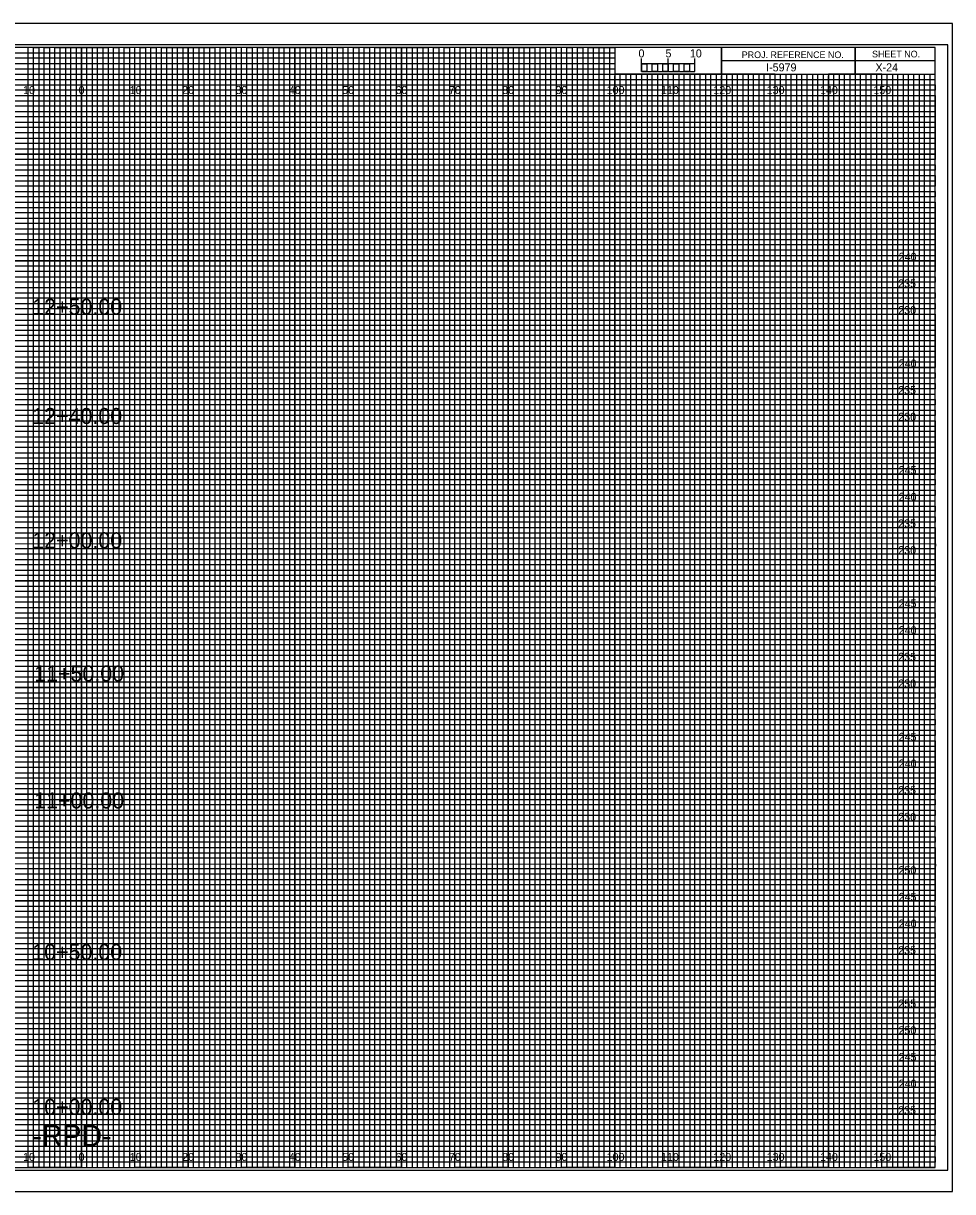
# Model space of a CAD drawing. Extents: x -13 to 323, y -5 to 215.
# Drawn here: x 149.1 to 323.3, y -4.5 to 214.5 of the extents above; entities that cross this region are included whole.
import ezdxf

# ---------------------------------------------------------------- set-up
doc = ezdxf.new("R2010")
doc.units = 0
for name, color, linetype in [('Exist CMT Pavement', 7, 'Continuous'), ('Exist Cross Section Cell', 7, 'Continuous'), ('Exist XS Center Line Elevation Label', 7, 'Continuous'), ('Exist XS Ground Line', 7, 'Continuous'), ('Prop CMT Concrete Structures', 7, 'Continuous'), ('Prop CMT Pvmt Course 1', 7, 'Continuous'), ('Prop CMT Pvmt Course 1 CG', 7, 'Continuous'), ('Prop CMT Pvmt Course 1 Wedge', 7, 'Continuous'), ('Prop CMT Pvmt Course 2', 7, 'Continuous'), ('Prop CMT Pvmt Course 2 Wedge', 7, 'Continuous'), ('Prop CMT Pvmt Course 3', 7, 'Continuous'), ('Prop CMT Pvmt Course 3 Wedge', 7, 'Continuous'), ('Prop CMT Pvmt Surface', 7, 'Continuous'), ('Prop CMT Pvmt Wedge Surface 1', 7, 'Continuous'), ('Prop CMT Pvmt Wedge Surface 2', 7, 'Continuous'), ('Prop CMT Pvmt Wedge Surface 3', 7, 'Continuous'), ('Prop CMT Subgrade Earthwork', 7, 'Continuous')]:
    doc.layers.add(name, color=color, linetype=linetype)

msp = doc.modelspace()

# ---------------------------------------------------------------- linework, layer by layer
at = {"layer": 'Exist CMT Pavement'}
for p, q in [((323.3, 214.5), (-13.4, 214.5)), ((-13.4, -4.5), (323.3, -4.5))]:
    msp.add_line(p, q, dxfattribs=at)
at = {"layer": 'Exist XS Center Line Elevation Label'}
for points in [[(145, 0), (155, 0), (155, 210), (165, 210), (165, 0), (175, 0), (175, 210), (185, 210), (185, 0), (195, 0), (195, 210), (205, 210), (205, 0), (215, 0), (215, 210), (225, 210), (225, 0), (235, 0), (235, 210), (245, 210), (245, 0), (255, 0), (255, 210), (259.93, 210), (260, 210), (260, 205), (264.99, 205), (264.99, 0), (275, 0), (275, 205), (285, 205), (285, 0), (295, 0), (295, 205), (305, 205), (305, 0), (315, 0), (315, 205)], [(0, 205), (275, 205)], [(0, 185), (320, 185), (320, 195), (0, 195)], [(0, 165), (320, 165), (320, 175), (0, 175)], [(0, 145), (320, 145), (320, 155), (0, 155)], [(0, 125), (320, 125), (320, 135), (0, 135)], [(0, 105), (320, 105), (320, 115), (0, 115)], [(0, 85), (320, 85), (320, 95), (0, 95)], [(0, 65), (320, 65), (320, 75), (0, 75)], [(0, 45), (320, 45), (320, 55), (0, 55)], [(0, 25), (320, 25), (320, 35), (0, 35)], [(0, 5), (320, 5), (320, 15), (0, 15)]]:
    msp.add_lwpolyline(points, dxfattribs=at)
at = {"layer": 'Exist XS Ground Line'}
for p, q in [((150, 210), (140, 210)), ((150, 0), (150, 210)), ((170, 210), (160, 210)), ((160, 210), (160, 0)), ((170, 0), (170, 210)), ((190, 210), (180, 210)), ((180, 210), (180, 0)), ((190, 0), (190, 210)), ((210, 210), (200, 210)), ((200, 210), (200, 0)), ((210, 0), (210, 210)), ((230, 210), (220, 210)), ((220, 210), (220, 0)), ((230, 0), (230, 210)), ((250, 210), (240, 210)), ((240, 210), (240, 0)), ((250, 0), (250, 210)), ((260, 210), (260, 0)), ((270, 0), (270, 205)), ((290, 205), (280, 205)), ((280, 205), (280, 0)), ((290, 0), (290, 205)), ((310, 205), (300, 205)), ((300, 205), (300, 0)), ((310, 0), (310, 205)), ((160, 0), (150, 0)), ((180, 0), (170, 0)), ((200, 0), (190, 0)), ((220, 0), (210, 0)), ((240, 0), (230, 0)), ((260, 0), (250, 0)), ((280, 0), (270, 0)), ((300, 0), (290, 0)), ((320, 0), (310, 0)), ((320, 0), (320, 0))]:
    msp.add_line(p, q, dxfattribs=at)
for points in [[(0, 200), (320, 200), (320, 190), (0, 190)], [(0, 180), (320, 180), (320, 170), (0, 170)], [(0, 160), (320, 160), (320, 150), (0, 150)], [(0, 140), (320, 140), (320, 130), (0, 130)], [(0, 120), (320, 120), (320, 110), (0, 110)], [(0, 100), (320, 100), (320, 90), (0, 90)], [(0, 80), (320, 80), (320, 70), (0, 70)], [(0, 60), (320, 60), (320, 50), (0, 50)], [(0, 40), (320, 40), (320, 30), (0, 30)], [(0, 20), (320, 20), (320, 10), (0, 10)]]:
    msp.add_lwpolyline(points, dxfattribs=at)
at = {"layer": 'Prop CMT Concrete Structures'}
for p, q in [((150, 0), (150, 210)), ((160, 0), (160, 210)), ((170, 0), (170, 210)), ((180, 0), (180, 210)), ((190, 0), (190, 210)), ((200, 0), (200, 210)), ((210, 0), (210, 210)), ((220, 0), (220, 210)), ((230, 0), (230, 210)), ((240, 0), (240, 210)), ((250, 0), (250, 210)), ((260, 0), (260, 204.69)), ((270, 0), (270, 204.69)), ((280, 0), (280, 204.69)), ((290, 0), (290, 204.69)), ((300, 0), (300, 204.69)), ((310, 0), (310, 204.69)), ((0, 200), (320, 200)), ((0, 190), (320, 190)), ((0, 180), (320, 180)), ((0, 170), (320, 170)), ((0, 160), (320, 160)), ((0, 150), (320, 150)), ((0, 140), (320, 140)), ((0, 130), (320, 130)), ((0, 120), (320, 120)), ((0, 110), (320, 110)), ((0, 100), (320, 100)), ((0, 90), (320, 90)), ((0, 80), (320, 80)), ((0, 70), (320, 70)), ((0, 60), (320, 60)), ((0, 50), (320, 50)), ((0, 40), (320, 40)), ((0, 30), (320, 30)), ((0, 20), (320, 20)), ((0, 10), (320, 10))]:
    msp.add_line(p, q, dxfattribs=at)
at = {"layer": 'Prop CMT Pvmt Course 1 Wedge'}
for p, q in [((265, 205.49), (265, 207.9)), ((265, 206.9), (265, 207.9)), ((270, 205.49), (270, 207.9)), ((275, 205.49), (275, 207.9)), ((275, 206.9), (275, 207.9))]:
    msp.add_line(p, q, dxfattribs=at)
for points in [[(275, 206.9), (265, 206.9), (265, 205.49), (275, 205.49)], [(265, 206.9), (266, 206.9), (266, 205.49), (265, 205.49)], [(267, 206.9), (268, 206.9), (268, 205.49), (267, 205.49)], [(269, 206.9), (270, 206.9), (270, 205.49), (269, 205.49)], [(271, 206.9), (272, 206.9), (272, 205.49), (271, 205.49)], [(273, 206.9), (274, 206.9), (274, 205.49), (273, 205.49)]]:
    msp.add_lwpolyline(points, close=True, dxfattribs=at)
at = {"layer": 'Prop CMT Pvmt Course 2'}
for p, q in [((0, 209), (260, 209)), ((260, 209), (260, 207.98)), ((260, 207.98), (0, 207.98)), ((0, 207), (260, 207)), ((260, 205.89), (0, 205.89)), ((260, 207), (260, 205.89)), ((0, 204), (320, 204))]:
    msp.add_line(p, q, dxfattribs=at)
for points in [[(0, 203), (270, 203), (320, 203), (320, 202), (0, 202)], [(0, 201), (320, 201), (320, 199), (0, 199)], [(0, 198), (320, 198), (320, 197), (0, 196.98)], [(0, 196), (320, 196), (320, 194), (0, 194)], [(0, 193), (320, 193), (320, 192), (0, 192)], [(0, 191), (320, 191), (320, 189), (0, 189)], [(0, 188), (320, 188), (320, 187), (0, 187)], [(0, 186), (320, 186), (320, 184), (0, 184)], [(0, 183), (320, 183), (320, 182), (0, 182)], [(0, 181), (320, 181), (320, 179), (0, 179)], [(0, 178), (320, 178), (320, 177), (0, 177)], [(0, 176), (320, 176), (320, 173.95), (320, 173), (320, 172), (0, 172)], [(0, 174), (320, 174), (320, 173), (0, 173)], [(0, 171), (320, 171), (320, 169), (0, 169.03)], [(0, 169.03), (320, 169), (320, 168), (0, 168)], [(0, 167), (320, 167), (320, 166), (0, 166)], [(0, 164), (320, 164), (320, 163), (0, 163)], [(0, 162), (320, 162), (320, 161), (0, 161)], [(-0.07, 158.89), (320, 158.89), (320, 157.88), (-0.07, 157.88)], [(0, 157), (320, 157), (320, 156), (0, 156)], [(0, 154), (320, 154), (320, 153), (0, 153)], [(0, 152), (320, 152), (320, 151), (0, 151)], [(0, 149), (320, 149), (320, 148), (0, 148)], [(0, 147), (320, 147), (320, 146), (0, 146)], [(0, 144), (320, 144), (320, 143), (0, 143)], [(0, 142), (320, 142), (320, 141), (0, 141)], [(0, 139), (320, 139), (319.99, 137.98), (0, 138)], [(0, 137), (320, 137), (320, 136), (0, 136)], [(0, 134), (320, 134), (320, 133), (0, 133)], [(0, 132), (320, 132), (320, 131), (0, 131)], [(0, 129), (320, 129), (320, 128), (0, 128)], [(0, 127), (320, 127), (320, 126), (0, 126)], [(0, 124), (320, 124), (320, 123), (0, 123)], [(0, 122), (320, 122), (320, 121), (0, 121)], [(0, 119), (320, 119), (320, 118), (0, 118)], [(0, 116.99), (320.07, 116.91), (320, 116), (0, 116)], [(0, 114), (320, 114), (320, 113), (0, 113)], [(0, 112), (320, 112), (320, 111), (0, 111)], [(0, 109), (320, 109), (320, 108), (0, 108)], [(0, 107), (320, 107), (320, 106), (0, 106)], [(0, 104), (320, 104), (320, 103), (0, 103)], [(0, 102), (320, 102), (320, 101), (0, 101)], [(0, 99), (320, 99), (320, 98), (0, 98)], [(0, 97), (320, 97), (320, 96), (0, 96)], [(0, 94), (320, 94), (320, 93), (0, 93)], [(0, 92), (320, 92), (320, 91), (0, 91)], [(0, 89), (320, 89), (320, 88), (0, 88)], [(0, 87), (320, 87), (320, 86), (0, 86)], [(0, 84), (320, 84), (320, 83), (0, 83)], [(0, 82), (320, 82), (320, 81), (0, 81)], [(0, 79), (320, 79), (319.99, 77.98), (0, 78)], [(0, 77), (320, 77), (320, 76), (0, 76)], [(0, 74), (320, 74), (320, 73), (0, 73)], [(0, 72), (320, 72), (320, 71), (0, 71)], [(0, 69), (320, 69), (320, 68), (0, 68)], [(0, 67), (320, 67), (320, 66), (0, 66)], [(0, 64), (320, 64), (320, 63), (0, 63)], [(0, 62), (320, 62), (320, 61), (0, 61)], [(0, 59), (320, 59), (320, 58), (0, 58)], [(0, 56.99), (320.07, 56.91), (320, 56), (0, 56)], [(0, 54), (320, 54), (320, 53), (0, 53)], [(0, 52), (320, 52), (320, 51), (0, 51)], [(0, 49), (320, 49), (320, 48), (0, 48)], [(0, 47), (320, 47), (320, 46), (0, 46)], [(0, 44), (320, 44), (320, 43), (0, 43)], [(0, 42), (320, 42), (320, 41), (0, 41)], [(0, 39), (320, 39), (320, 38), (0, 38)], [(0, 37), (320, 37), (320, 36), (0, 36)], [(0, 34), (320, 34), (320, 33), (0, 33)], [(0, 32), (320, 32), (320, 31), (0, 31)], [(0, 29), (320, 29), (320, 28), (0, 28)], [(0, 27), (320, 27), (320, 26), (0, 26)], [(0, 24), (320, 24), (320, 23), (0, 23)], [(0, 22), (320, 22), (320, 21), (0, 21)], [(0, 19), (320, 19), (320, 18), (0, 18)], [(0, 17), (320, 17), (320, 16), (0, 16)], [(0, 14), (320, 14), (320, 13), (0, 13)], [(0, 12), (320, 12), (320, 11), (0, 11)], [(0, 9), (320, 9), (320, 8), (0, 8)], [(0, 7), (320, 7), (320, 6), (0, 6)], [(0, 4), (320, 4), (320, 3), (0, 3)], [(0, 2), (320, 2), (320, 1), (0, 1)]]:
    msp.add_lwpolyline(points, dxfattribs=at)
at = {"layer": 'Prop CMT Pvmt Course 2 Wedge'}
msp.add_lwpolyline([(-13.4, -4.5), (323.3, -4.5), (323.3, 214.5), (-13.4, 214.5)], close=True, dxfattribs=at)
at = {"layer": 'Prop CMT Pvmt Course 3'}
for p, q in [((305, 210), (305, 205)), ((305, 205), (305, 210)), ((280, 207.5), (280, 205)), ((320, 207.49), (280, 207.49)), ((280, 205), (320, 205))]:
    msp.add_line(p, q, dxfattribs=at)
for points in [[(320, 210), (0, 210), (0, 0), (320, 0)], [(280, 210), (260, 210), (260, 205.03), (280, 205.03)], [(320, 210), (280, 210), (280, 205), (320, 205)]]:
    msp.add_lwpolyline(points, close=True, dxfattribs=at)
at = {"layer": 'Prop CMT Pvmt Course 3 Wedge'}
msp.add_lwpolyline([(-10.8, -0.5), (322.4, -0.5), (322.4, 210.5), (-10.8, 210.5)], close=True, dxfattribs=at)
at = {"layer": 'Prop CMT Subgrade Earthwork'}
for p, q in [((267, 205), (266.01, 205)), ((266.01, 205), (266.01, 0)), ((267, 0), (267, 205)), ((269, 205), (268, 205)), ((268, 205), (268, 0)), ((269, 0), (269, 205)), ((266.01, 0), (265, 0)), ((268, 0), (267, 0))]:
    msp.add_line(p, q, dxfattribs=at)
for points in [[(150, 0), (151, 0), (151, 210), (152, 210), (152, 0)], [(152, 0), (153, 0), (153, 210), (154, 210), (154, 0)], [(155, 0), (156, 0), (156, 210), (157, 210), (157, 0)], [(157, 0), (158, 0), (158, 210), (159, 210), (159, 0)], [(160, 0), (161, 0), (161, 210), (162, 210), (162, 0)], [(162, 0), (163, 0), (163, 210), (164, 210), (164, 0)], [(165, 0), (166, 0), (166, 210), (167, 210), (167, 0)], [(167, 0), (168, 0), (168, 210), (169, 210), (169, 0)], [(170, 0), (171, 0), (171, 210), (172, 210), (172, 0)], [(172, 0), (173, 0), (173, 210), (174, 210), (174, 0)], [(175, 0), (176, 0), (176, 210), (177, 210), (177, 0)], [(177, 0), (178, 0), (178, 210), (179, 210), (179, 0)], [(180, 0), (181, 0), (181, 210), (182, 210), (182, 0)], [(182, 0), (183, 0), (183, 210), (184, 210), (184, 0)], [(185, 0), (186, 0), (186, 210), (187, 210), (187, 0)], [(187, 0), (188, 0), (188, 210), (189, 210), (189, 0)], [(190, 0), (191, 0), (191, 210), (192, 210), (192, 0)], [(192, 0), (193, 0), (193, 210), (194, 210), (194, 0)], [(195, 0), (196, 0), (196, 210), (197, 210), (197, 0)], [(197, 0), (198, 0), (198, 210), (199, 210), (199, 0)], [(200, 0), (201, 0), (201, 210), (202, 210), (202, 0)], [(202, 0), (203, 0), (203, 210), (204, 210), (204, 0)], [(205, 0), (206, 0), (206, 210), (207, 210), (207, 0)], [(207, 0), (208, 0), (208, 210), (209, 210), (209, 0)], [(210, 0), (211, 0), (211, 210), (212, 210), (212, 0)], [(212, 0), (213, 0), (213, 210), (214, 210), (214, 0)], [(215, 0), (216, 0), (216, 210), (217, 210), (217, 0)], [(217, 0), (218, 0), (218, 210), (219, 210), (219, 0)], [(220, 0), (221, 0), (221, 210), (222, 210), (222, 0)], [(222, 0), (223, 0), (223, 210), (224, 210), (224, 0)], [(225, 0), (226, 0), (226, 210), (227, 210), (227, 0)], [(227, 0), (228, 0), (228, 210), (229, 210), (229, 0)], [(230, 0), (231, 0), (231, 210), (232, 210), (232, 0)], [(232, 0), (233, 0), (233, 210), (234, 210), (234, 0)], [(235, 0), (236, 0), (236, 210), (237, 210), (237, 0)], [(237, 0), (238, 0), (238, 210), (239, 210), (239, 0)], [(240, 0), (241, 0), (241, 210), (242, 210), (242, 0)], [(242, 0), (243, 0), (243, 210), (244, 210), (244, 0)], [(245, 0), (246, 0), (246, 210), (247, 210), (247, 0)], [(247, 0), (248, 0), (248, 210), (249, 210), (249, 0)], [(250, 0), (251, 0), (251, 210), (252, 210), (252, 0)], [(252, 0), (253, 0), (253, 210), (254, 210), (254, 0)], [(255, 0), (256, 0), (256, 210), (257, 210), (257, 0)], [(257, 0), (258, 0), (258, 210), (259, 210), (259, 0)], [(260, 0), (261, 0), (261, 205), (262.02, 205), (262.02, 0)], [(262, 0), (263, 0), (263, 205), (263.99, 205), (263.99, 0)], [(270, 0), (270.98, 0), (270.98, 205), (272, 205), (272, 0)], [(272, 0), (273, 0), (273, 205), (274.05, 205), (274.05, 0)], [(275, 0), (276, 0), (276, 205), (277, 205), (277, 0)], [(277, 0), (278, 0), (278, 205), (279, 205), (279, 0)], [(280, 0), (281, 0), (281, 205), (282, 205), (282, 0)], [(282, 0), (283, 0), (283, 205), (284, 205), (284, 0)], [(285, 0), (286, 0), (286, 205), (287, 205), (287, 0)], [(287, 0), (288, 0), (288, 205), (289, 205), (289, 0)], [(290, 0), (291, 0), (291, 205), (292, 205), (292, 0)], [(292, 0), (293, 0), (293, 205), (294, 205), (294, 0)], [(295, 0), (296, 0), (296, 205), (297, 205), (297, 0)], [(297, 0), (298, 0), (298, 205), (299, 205), (299, 0)], [(300, 0), (301, 0), (301, 205), (302, 205), (302, 0)], [(302, 0), (303, 0), (303, 205), (304, 205), (304, 0)], [(305, 0), (306, 0), (306, 205), (307, 205), (307, 0)], [(307, 0), (308, 0), (308, 205), (309, 205), (309, 0)], [(310, 0), (311, 0), (311, 205), (312, 205), (312, 0)], [(312, 0), (313, 0), (313, 205), (314, 205), (314, 0)], [(315, 0), (316, 0), (316, 205), (317, 205), (317, 0)], [(317, 0), (318, 0), (318, 205), (319, 205), (319, 0)]]:
    msp.add_lwpolyline(points, dxfattribs=at)

# ---------------------------------------------------------------- texts
at = {"layer": 'Exist Cross Section Cell'}
for s, p in [('10', (149.04, 201.25)), ('0', (159.45, 201.25)), ('0', (159.45, 201.25)), ('10', (169.04, 201.25)), ('20', (178.86, 201.25)), ('30', (188.86, 201.25)), ('40', (198.86, 201.25)), ('50', (208.86, 201.25)), ('60', (218.86, 201.25)), ('70', (228.86, 201.25)), ('80', (238.86, 201.25)), ('90', (248.86, 201.25)), ('100', (258.44, 201.25)), ('110', (268.62, 201.25)), ('120', (278.44, 201.25)), ('130', (288.44, 201.25)), ('140', (298.44, 201.25)), ('150', (308.44, 201.25)), ('10', (149.04, 1.25)), ('0', (159.45, 1.25)), ('0', (159.45, 1.25)), ('10', (169.04, 1.25)), ('20', (178.86, 1.25)), ('30', (188.86, 1.25)), ('40', (198.86, 1.25)), ('50', (208.86, 1.25)), ('60', (218.86, 1.25)), ('70', (228.86, 1.25)), ('80', (238.86, 1.25)), ('90', (248.86, 1.25)), ('100', (258.44, 1.25)), ('110', (268.62, 1.25)), ('120', (278.44, 1.25)), ('130', (288.44, 1.25)), ('140', (298.44, 1.25)), ('150', (308.44, 1.25))]:
    msp.add_text(s, height=1.5, dxfattribs=at).set_placement(p)
at = {"layer": 'Prop CMT Pvmt Course 1'}
for s, p in [('5', (269.47, 208.12)), ('10', (274.04, 208.12))]:
    msp.add_text(s, height=1.5, dxfattribs=at).set_placement(p)
at = {"layer": 'Prop CMT Pvmt Course 1 CG'}
for s, p in [('12+50.00', (150.77, 159.88)), ('12+40.00', (150.77, 139.4)), ('12+00.00', (150.77, 116.09)), ('11+50.00', (151.13, 91.13)), ('11+00.00', (151.13, 67.33)), ('10+50.00', (150.77, 38.92)), ('10+00.00', (150.77, 9.88))]:
    msp.add_text(s, height=3, dxfattribs=at).set_placement(p)
at = {"layer": 'Prop CMT Pvmt Course 1 Wedge'}
msp.add_text('0', height=1.5, dxfattribs=at).set_placement((264.41, 208.12))
at = {"layer": 'Prop CMT Pvmt Course 3'}
for s, p in [('PROJ. REFERENCE NO.', (283.77, 207.99)), ('SHEET NO.', (308.19, 208.12))]:
    msp.add_text(s, height=1.25, dxfattribs=at).set_placement(p)
at = {"layer": 'Prop CMT Pvmt Surface'}
for s, p in [('240', (313.19, 170)), ('235', (313.09, 165)), ('230', (313.11, 160)), ('240', (313.19, 150)), ('235', (313.09, 145)), ('230', (313.11, 140)), ('245', (313.18, 130)), ('240', (313.19, 125)), ('235', (313.09, 120)), ('230', (313.11, 115)), ('245', (313.18, 105)), ('240', (313.19, 100)), ('235', (313.09, 95)), ('230', (313.11, 90)), ('245', (313.18, 80)), ('240', (313.19, 75)), ('235', (313.09, 70)), ('230', (313.11, 65)), ('250', (313.15, 55)), ('245', (313.18, 50)), ('240', (313.19, 45)), ('235', (313.09, 40)), ('255', (313.13, 30)), ('250', (313.15, 25)), ('245', (313.18, 20)), ('240', (313.19, 15)), ('235', (313.09, 10))]:
    msp.add_text(s, height=1.5, dxfattribs=at).set_placement(p)
at = {"layer": 'Prop CMT Pvmt Wedge Surface 1'}
msp.add_text('X-24', height=1.5, dxfattribs=at).set_placement((308.83, 205.5))
at = {"layer": 'Prop CMT Pvmt Wedge Surface 2'}
msp.add_text('I-5979', height=1.5, dxfattribs=at).set_placement((288.34, 205.5))
at = {"layer": 'Prop CMT Pvmt Wedge Surface 3'}
msp.add_text('-RPD-', height=4, dxfattribs=at).set_placement((150.78, 4))

doc.saveas('drawing.dxf')
